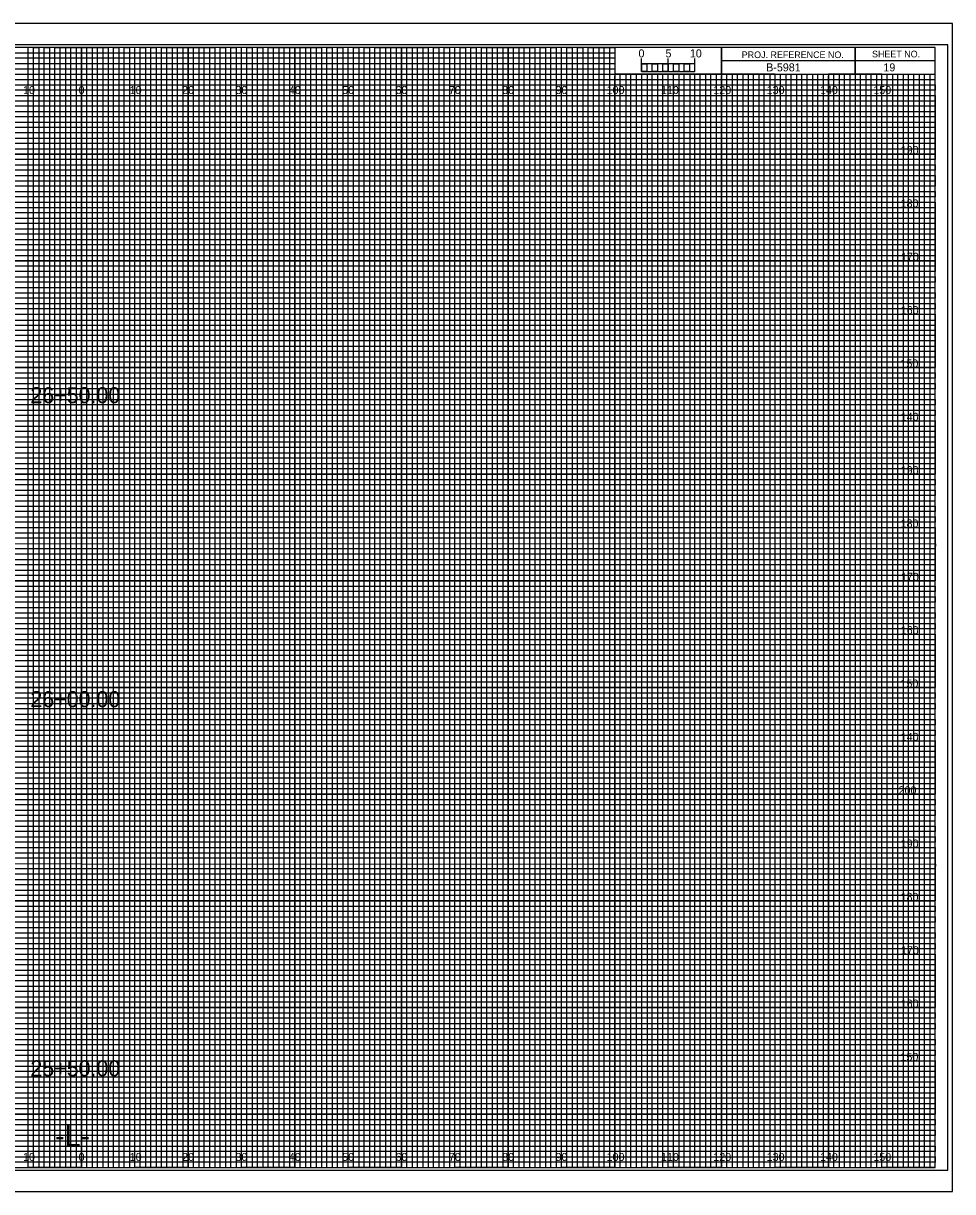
# Model space of a CAD drawing. Extents: x -13 to 323, y -5 to 4174.
# Drawn here: x 149.1 to 323.3, y 2855.5 to 3074.5 of the extents above; entities that cross this region are included whole.
import ezdxf

# ---------------------------------------------------------------- set-up
doc = ezdxf.new("R2010")
doc.units = 0
for name, color, linetype in [('Exist Cross Section Cell', 7, 'Continuous'), ('Exist XS Center Line Elevation Label', 7, 'Continuous'), ('Exist XS Ground Line', 7, 'Continuous'), ('Prop CMT Concrete Structures', 7, 'Continuous'), ('Prop CMT Guardrail Graphics', 7, 'Continuous'), ('Prop CMT Pvmt Course 1', 7, 'Continuous'), ('Prop CMT Pvmt Course 2', 7, 'Continuous'), ('Prop CMT Pvmt Course 3', 7, 'Continuous'), ('Prop CMT Pvmt Surface', 7, 'Continuous'), ('Prop CMT Shld Paved Course 1', 7, 'Continuous'), ('Prop CMT Shld Paved Course 2', 7, 'Continuous'), ('Prop CMT Shld Paved Course 3', 7, 'Continuous'), ('Prop CMT Subgrade Earthwork', 7, 'Continuous'), ('Prop XS Ditch Standard Text', 7, 'Continuous'), ('Prop XS SE Text', 7, 'Continuous'), ('Prop XS Side Slope Text', 7, 'Continuous'), ('Scratch_Level_0', 7, 'Continuous')]:
    doc.layers.add(name, color=color, linetype=linetype)

msp = doc.modelspace()

# ---------------------------------------------------------------- linework, layer by layer
at = {"layer": 'Exist XS Center Line Elevation Label'}
for points in [[(145, 2860), (155, 2860), (155, 3070), (165, 3070), (165, 2860), (175, 2860), (175, 3070), (185, 3070), (185, 2860), (195, 2860), (195, 3070), (205, 3070), (205, 2860), (215, 2860), (215, 3070), (225, 3070), (225, 2860), (235, 2860), (235, 3070), (245, 3070), (245, 2860), (255, 2860), (255, 3070), (259.93, 3070), (260, 3070), (260, 3065), (264.99, 3065), (264.99, 2860), (275, 2860), (275, 3065), (285, 3065), (285, 2860), (295, 2860), (295, 3065), (305, 3065), (305, 2860), (315, 2860), (315, 3065)], [(0, 3065), (275, 3065)], [(0, 3045), (320, 3045), (320, 3055), (0, 3055)], [(0, 3025), (320, 3025), (320, 3035), (0, 3035)], [(0, 3005), (320, 3005), (320, 3015), (0, 3015)], [(0, 2985), (320, 2985), (320, 2995), (0, 2995)], [(0, 2965), (320, 2965), (320, 2975), (0, 2975)], [(0, 2945), (320, 2945), (320, 2955), (0, 2955)], [(0, 2925), (320, 2925), (320, 2935), (0, 2935)], [(0, 2905), (320, 2905), (320, 2915), (0, 2915)], [(0, 2885), (320, 2885), (320, 2895), (0, 2895)], [(0, 2865), (320, 2865), (320, 2875), (0, 2875)]]:
    msp.add_lwpolyline(points, dxfattribs=at)
at = {"layer": 'Exist XS Ground Line'}
for p, q in [((150, 3070), (140, 3070)), ((150, 2860), (150, 3070)), ((170, 3070), (160, 3070)), ((160, 3070), (160, 2860)), ((170, 2860), (170, 3070)), ((190, 3070), (180, 3070)), ((180, 3070), (180, 2860)), ((190, 2860), (190, 3070)), ((210, 3070), (200, 3070)), ((200, 3070), (200, 2860)), ((210, 2860), (210, 3070)), ((230, 3070), (220, 3070)), ((220, 3070), (220, 2860)), ((230, 2860), (230, 3070)), ((250, 3070), (240, 3070)), ((240, 3070), (240, 2860)), ((250, 2860), (250, 3070)), ((260, 3070), (260, 2860)), ((270, 2860), (270, 3065)), ((290, 3065), (280, 3065)), ((280, 3065), (280, 2860)), ((290, 2860), (290, 3065)), ((310, 3065), (300, 3065)), ((300, 3065), (300, 2860)), ((310, 2860), (310, 3065)), ((160, 2860), (150, 2860)), ((180, 2860), (170, 2860)), ((200, 2860), (190, 2860)), ((220, 2860), (210, 2860)), ((240, 2860), (230, 2860)), ((260, 2860), (250, 2860)), ((280, 2860), (270, 2860)), ((300, 2860), (290, 2860)), ((320, 2860), (310, 2860)), ((320, 2860), (320, 2860))]:
    msp.add_line(p, q, dxfattribs=at)
for points in [[(0, 3060), (320, 3060), (320, 3050), (0, 3050)], [(0, 3040), (320, 3040), (320, 3030), (0, 3030)], [(0, 3020), (320, 3020), (320, 3010), (0, 3010)], [(0, 3000), (320, 3000), (320, 2990), (0, 2990)], [(0, 2980), (320, 2980), (320, 2970), (0, 2970)], [(0, 2960), (320, 2960), (320, 2950), (0, 2950)], [(0, 2940), (320, 2940), (320, 2930), (0, 2930)], [(0, 2920), (320, 2920), (320, 2910), (0, 2910)], [(0, 2900), (320, 2900), (320, 2890), (0, 2890)], [(0, 2880), (320, 2880), (320, 2870), (0, 2870)]]:
    msp.add_lwpolyline(points, dxfattribs=at)
at = {"layer": 'Prop CMT Pvmt Course 1'}
for p, q in [((323.3, 3074.5), (-13.4, 3074.5)), ((-13.4, 2855.5), (323.3, 2855.5))]:
    msp.add_line(p, q, dxfattribs=at)
at = {"layer": 'Prop CMT Pvmt Course 2'}
msp.add_lwpolyline([(-13.4, 2855.5), (323.3, 2855.5), (323.3, 3074.5), (-13.4, 3074.5)], close=True, dxfattribs=at)
at = {"layer": 'Prop CMT Pvmt Course 3'}
msp.add_lwpolyline([(-10.8, 2859.5), (322.4, 2859.5), (322.4, 3070.5), (-10.8, 3070.5)], close=True, dxfattribs=at)
at = {"layer": 'Prop CMT Shld Paved Course 1'}
for p, q in [((305, 3070), (305, 3065)), ((305, 3065), (305, 3070)), ((280, 3067.5), (280, 3065)), ((320, 3067.49), (280, 3067.49)), ((280, 3065), (320, 3065))]:
    msp.add_line(p, q, dxfattribs=at)
for points in [[(320, 3070), (0, 3070), (0, 2860), (320, 2860)], [(280, 3070), (260, 3070), (260, 3065.03), (280, 3065.03)], [(320, 3070), (280, 3070), (280, 3065), (320, 3065)]]:
    msp.add_lwpolyline(points, close=True, dxfattribs=at)
at = {"layer": 'Prop CMT Shld Paved Course 2'}
for p, q in [((267, 3065), (266.01, 3065)), ((266.01, 3065), (266.01, 2860)), ((267, 2860), (267, 3065)), ((269, 3065), (268, 3065)), ((268, 3065), (268, 2860)), ((269, 2860), (269, 3065)), ((266.01, 2860), (265, 2860)), ((268, 2860), (267, 2860))]:
    msp.add_line(p, q, dxfattribs=at)
for points in [[(150, 2860), (151, 2860), (151, 3070), (152, 3070), (152, 2860)], [(152, 2860), (153, 2860), (153, 3070), (154, 3070), (154, 2860)], [(155, 2860), (156, 2860), (156, 3070), (157, 3070), (157, 2860)], [(157, 2860), (158, 2860), (158, 3070), (159, 3070), (159, 2860)], [(160, 2860), (161, 2860), (161, 3070), (162, 3070), (162, 2860)], [(162, 2860), (163, 2860), (163, 3070), (164, 3070), (164, 2860)], [(165, 2860), (166, 2860), (166, 3070), (167, 3070), (167, 2860)], [(167, 2860), (168, 2860), (168, 3070), (169, 3070), (169, 2860)], [(170, 2860), (171, 2860), (171, 3070), (172, 3070), (172, 2860)], [(172, 2860), (173, 2860), (173, 3070), (174, 3070), (174, 2860)], [(175, 2860), (176, 2860), (176, 3070), (177, 3070), (177, 2860)], [(177, 2860), (178, 2860), (178, 3070), (179, 3070), (179, 2860)], [(180, 2860), (181, 2860), (181, 3070), (182, 3070), (182, 2860)], [(182, 2860), (183, 2860), (183, 3070), (184, 3070), (184, 2860)], [(185, 2860), (186, 2860), (186, 3070), (187, 3070), (187, 2860)], [(187, 2860), (188, 2860), (188, 3070), (189, 3070), (189, 2860)], [(190, 2860), (191, 2860), (191, 3070), (192, 3070), (192, 2860)], [(192, 2860), (193, 2860), (193, 3070), (194, 3070), (194, 2860)], [(195, 2860), (196, 2860), (196, 3070), (197, 3070), (197, 2860)], [(197, 2860), (198, 2860), (198, 3070), (199, 3070), (199, 2860)], [(200, 2860), (201, 2860), (201, 3070), (202, 3070), (202, 2860)], [(202, 2860), (203, 2860), (203, 3070), (204, 3070), (204, 2860)], [(205, 2860), (206, 2860), (206, 3070), (207, 3070), (207, 2860)], [(207, 2860), (208, 2860), (208, 3070), (209, 3070), (209, 2860)], [(210, 2860), (211, 2860), (211, 3070), (212, 3070), (212, 2860)], [(212, 2860), (213, 2860), (213, 3070), (214, 3070), (214, 2860)], [(215, 2860), (216, 2860), (216, 3070), (217, 3070), (217, 2860)], [(217, 2860), (218, 2860), (218, 3070), (219, 3070), (219, 2860)], [(220, 2860), (221, 2860), (221, 3070), (222, 3070), (222, 2860)], [(222, 2860), (223, 2860), (223, 3070), (224, 3070), (224, 2860)], [(225, 2860), (226, 2860), (226, 3070), (227, 3070), (227, 2860)], [(227, 2860), (228, 2860), (228, 3070), (229, 3070), (229, 2860)], [(230, 2860), (231, 2860), (231, 3070), (232, 3070), (232, 2860)], [(232, 2860), (233, 2860), (233, 3070), (234, 3070), (234, 2860)], [(235, 2860), (236, 2860), (236, 3070), (237, 3070), (237, 2860)], [(237, 2860), (238, 2860), (238, 3070), (239, 3070), (239, 2860)], [(240, 2860), (241, 2860), (241, 3070), (242, 3070), (242, 2860)], [(242, 2860), (243, 2860), (243, 3070), (244, 3070), (244, 2860)], [(245, 2860), (246, 2860), (246, 3070), (247, 3070), (247, 2860)], [(247, 2860), (248, 2860), (248, 3070), (249, 3070), (249, 2860)], [(250, 2860), (251, 2860), (251, 3070), (252, 3070), (252, 2860)], [(252, 2860), (253, 2860), (253, 3070), (254, 3070), (254, 2860)], [(255, 2860), (256, 2860), (256, 3070), (257, 3070), (257, 2860)], [(257, 2860), (258, 2860), (258, 3070), (259, 3070), (259, 2860)], [(260, 2860), (261, 2860), (261, 3065), (262.02, 3065), (262.02, 2860)], [(262, 2860), (263, 2860), (263, 3065), (263.99, 3065), (263.99, 2860)], [(270, 2860), (270.98, 2860), (270.98, 3065), (272, 3065), (272, 2860)], [(272, 2860), (273, 2860), (273, 3065), (274.05, 3065), (274.05, 2860)], [(275, 2860), (276, 2860), (276, 3065), (277, 3065), (277, 2860)], [(277, 2860), (278, 2860), (278, 3065), (279, 3065), (279, 2860)], [(280, 2860), (281, 2860), (281, 3065), (282, 3065), (282, 2860)], [(282, 2860), (283, 2860), (283, 3065), (284, 3065), (284, 2860)], [(285, 2860), (286, 2860), (286, 3065), (287, 3065), (287, 2860)], [(287, 2860), (288, 2860), (288, 3065), (289, 3065), (289, 2860)], [(290, 2860), (291, 2860), (291, 3065), (292, 3065), (292, 2860)], [(292, 2860), (293, 2860), (293, 3065), (294, 3065), (294, 2860)], [(295, 2860), (296, 2860), (296, 3065), (297, 3065), (297, 2860)], [(297, 2860), (298, 2860), (298, 3065), (299, 3065), (299, 2860)], [(300, 2860), (301, 2860), (301, 3065), (302, 3065), (302, 2860)], [(302, 2860), (303, 2860), (303, 3065), (304, 3065), (304, 2860)], [(305, 2860), (306, 2860), (306, 3065), (307, 3065), (307, 2860)], [(307, 2860), (308, 2860), (308, 3065), (309, 3065), (309, 2860)], [(310, 2860), (311, 2860), (311, 3065), (312, 3065), (312, 2860)], [(312, 2860), (313, 2860), (313, 3065), (314, 3065), (314, 2860)], [(315, 2860), (316, 2860), (316, 3065), (317, 3065), (317, 2860)], [(317, 2860), (318, 2860), (318, 3065), (319, 3065), (319, 2860)]]:
    msp.add_lwpolyline(points, dxfattribs=at)
at = {"layer": 'Prop CMT Shld Paved Course 3'}
for p, q in [((265, 3065.49), (265, 3067.9)), ((265, 3066.9), (265, 3067.9)), ((270, 3065.49), (270, 3067.9)), ((275, 3065.49), (275, 3067.9)), ((275, 3066.9), (275, 3067.9))]:
    msp.add_line(p, q, dxfattribs=at)
for points in [[(275, 3066.9), (265, 3066.9), (265, 3065.49), (275, 3065.49)], [(265, 3066.9), (266, 3066.9), (266, 3065.49), (265, 3065.49)], [(267, 3066.9), (268, 3066.9), (268, 3065.49), (267, 3065.49)], [(269, 3066.9), (270, 3066.9), (270, 3065.49), (269, 3065.49)], [(271, 3066.9), (272, 3066.9), (272, 3065.49), (271, 3065.49)], [(273, 3066.9), (274, 3066.9), (274, 3065.49), (273, 3065.49)]]:
    msp.add_lwpolyline(points, close=True, dxfattribs=at)
at = {"layer": 'Prop CMT Subgrade Earthwork'}
for p, q in [((150, 2860), (150, 3070)), ((160, 2860), (160, 3070)), ((170, 2860), (170, 3070)), ((180, 2860), (180, 3070)), ((190, 2860), (190, 3070)), ((200, 2860), (200, 3070)), ((210, 2860), (210, 3070)), ((220, 2860), (220, 3070)), ((230, 2860), (230, 3070)), ((240, 2860), (240, 3070)), ((250, 2860), (250, 3070)), ((260, 2860), (260, 3064.69)), ((270, 2860), (270, 3064.69)), ((280, 2860), (280, 3064.69)), ((290, 2860), (290, 3064.69)), ((300, 2860), (300, 3064.69)), ((310, 2860), (310, 3064.69)), ((0, 3060), (320, 3060)), ((0, 3050), (320, 3050)), ((0, 3040), (320, 3040)), ((0, 3030), (320, 3030)), ((0, 3020), (320, 3020)), ((0, 3010), (320, 3010)), ((0, 3000), (320, 3000)), ((0, 2990), (320, 2990)), ((0, 2980), (320, 2980)), ((0, 2970), (320, 2970)), ((0, 2960), (320, 2960)), ((0, 2950), (320, 2950)), ((0, 2940), (320, 2940)), ((0, 2930), (320, 2930)), ((0, 2920), (320, 2920)), ((0, 2910), (320, 2910)), ((0, 2900), (320, 2900)), ((0, 2890), (320, 2890)), ((0, 2880), (320, 2880)), ((0, 2870), (320, 2870))]:
    msp.add_line(p, q, dxfattribs=at)
at = {"layer": 'Scratch_Level_0'}
for p, q in [((0, 3069), (260, 3069)), ((260, 3069), (260, 3067.98)), ((260, 3067.98), (0, 3067.98)), ((0, 3067), (260, 3067)), ((260, 3067), (260, 3065.89)), ((260, 3065.89), (0, 3065.89)), ((0, 3064), (320, 3064))]:
    msp.add_line(p, q, dxfattribs=at)
for points in [[(0, 3063), (270, 3063), (320, 3063), (320, 3062), (0, 3062)], [(0, 3061), (320, 3061), (320, 3059), (0, 3059)], [(0, 3058), (320, 3058), (320, 3057), (0, 3056.98)], [(0, 3056), (320, 3056), (320, 3054), (0, 3054)], [(0, 3053), (320, 3053), (320, 3052), (0, 3052)], [(0, 3051), (320, 3051), (320, 3049), (0, 3049)], [(0, 3048), (320, 3048), (320, 3047), (0, 3047)], [(0, 3046), (320, 3046), (320, 3044), (0, 3044)], [(0, 3043), (320, 3043), (320, 3042), (0, 3042)], [(0, 3041), (320, 3041), (320, 3039), (0, 3039)], [(0, 3038), (320, 3038), (320, 3037), (0, 3037)], [(0, 3036), (320, 3036), (320, 3033.95), (320, 3033), (320, 3032), (0, 3032)], [(0, 3034), (320, 3034), (320, 3033), (0, 3033)], [(0, 3031), (320, 3031), (320, 3029), (0, 3029.03)], [(0, 3029.03), (320, 3029), (320, 3028), (0, 3028)], [(0, 3027), (320, 3027), (320, 3026), (0, 3026)], [(0, 3024), (320, 3024), (320, 3023), (0, 3023)], [(0, 3022), (320, 3022), (320, 3021), (0, 3021)], [(-0.07, 3018.89), (320, 3018.89), (320, 3017.88), (-0.07, 3017.88)], [(0, 3017), (320, 3017), (320, 3016), (0, 3016)], [(0, 3014), (320, 3014), (320, 3013), (0, 3013)], [(0, 3012), (320, 3012), (320, 3011), (0, 3011)], [(0, 3009), (320, 3009), (320, 3008), (0, 3008)], [(0, 3007), (320, 3007), (320, 3006), (0, 3006)], [(0, 3004), (320, 3004), (320, 3003), (0, 3003)], [(0, 3002), (320, 3002), (320, 3001), (0, 3001)], [(0, 2999), (320, 2999), (319.99, 2997.98), (0, 2998)], [(0, 2997), (320, 2997), (320, 2996), (0, 2996)], [(0, 2994), (320, 2994), (320, 2993), (0, 2993)], [(0, 2992), (320, 2992), (320, 2991), (0, 2991)], [(0, 2989), (320, 2989), (320, 2988), (0, 2988)], [(0, 2987), (320, 2987), (320, 2986), (0, 2986)], [(0, 2984), (320, 2984), (320, 2983), (0, 2983)], [(0, 2982), (320, 2982), (320, 2981), (0, 2981)], [(0, 2979), (320, 2979), (320, 2978), (0, 2978)], [(0, 2976.99), (320.07, 2976.91), (320, 2976), (0, 2976)], [(0, 2974), (320, 2974), (320, 2973), (0, 2973)], [(0, 2972), (320, 2972), (320, 2971), (0, 2971)], [(0, 2969), (320, 2969), (320, 2968), (0, 2968)], [(0, 2967), (320, 2967), (320, 2966), (0, 2966)], [(0, 2964), (320, 2964), (320, 2963), (0, 2963)], [(0, 2962), (320, 2962), (320, 2961), (0, 2961)], [(0, 2959), (320, 2959), (320, 2958), (0, 2958)], [(0, 2957), (320, 2957), (320, 2956), (0, 2956)], [(0, 2954), (320, 2954), (320, 2953), (0, 2953)], [(0, 2952), (320, 2952), (320, 2951), (0, 2951)], [(0, 2949), (320, 2949), (320, 2948), (0, 2948)], [(0, 2947), (320, 2947), (320, 2946), (0, 2946)], [(0, 2944), (320, 2944), (320, 2943), (0, 2943)], [(0, 2942), (320, 2942), (320, 2941), (0, 2941)], [(0, 2939), (320, 2939), (319.99, 2937.98), (0, 2938)], [(0, 2937), (320, 2937), (320, 2936), (0, 2936)], [(0, 2934), (320, 2934), (320, 2933), (0, 2933)], [(0, 2932), (320, 2932), (320, 2931), (0, 2931)], [(0, 2929), (320, 2929), (320, 2928), (0, 2928)], [(0, 2927), (320, 2927), (320, 2926), (0, 2926)], [(0, 2924), (320, 2924), (320, 2923), (0, 2923)], [(0, 2922), (320, 2922), (320, 2921), (0, 2921)], [(0, 2919), (320, 2919), (320, 2918), (0, 2918)], [(0, 2916.99), (320.07, 2916.91), (320, 2916), (0, 2916)], [(0, 2914), (320, 2914), (320, 2913), (0, 2913)], [(0, 2912), (320, 2912), (320, 2911), (0, 2911)], [(0, 2909), (320, 2909), (320, 2908), (0, 2908)], [(0, 2907), (320, 2907), (320, 2906), (0, 2906)], [(0, 2904), (320, 2904), (320, 2903), (0, 2903)], [(0, 2902), (320, 2902), (320, 2901), (0, 2901)], [(0, 2899), (320, 2899), (320, 2898), (0, 2898)], [(0, 2897), (320, 2897), (320, 2896), (0, 2896)], [(0, 2894), (320, 2894), (320, 2893), (0, 2893)], [(0, 2892), (320, 2892), (320, 2891), (0, 2891)], [(0, 2889), (320, 2889), (320, 2888), (0, 2888)], [(0, 2887), (320, 2887), (320, 2886), (0, 2886)], [(0, 2884), (320, 2884), (320, 2883), (0, 2883)], [(0, 2882), (320, 2882), (320, 2881), (0, 2881)], [(0, 2879), (320, 2879), (320, 2878), (0, 2878)], [(0, 2877), (320, 2877), (320, 2876), (0, 2876)], [(0, 2874), (320, 2874), (320, 2873), (0, 2873)], [(0, 2872), (320, 2872), (320, 2871), (0, 2871)], [(0, 2869), (320, 2869), (320, 2868), (0, 2868)], [(0, 2867), (320, 2867), (320, 2866), (0, 2866)], [(0, 2864), (320, 2864), (320, 2863), (0, 2863)], [(0, 2862), (320, 2862), (320, 2861), (0, 2861)]]:
    msp.add_lwpolyline(points, dxfattribs=at)

# ---------------------------------------------------------------- texts
at = {"layer": 'Exist Cross Section Cell'}
for s, p in [('10', (149.04, 3061.25)), ('0', (159.45, 3061.25)), ('0', (159.45, 3061.25)), ('10', (169.04, 3061.25)), ('20', (178.86, 3061.25)), ('30', (188.86, 3061.25)), ('40', (198.86, 3061.25)), ('50', (208.86, 3061.25)), ('60', (218.86, 3061.25)), ('70', (228.86, 3061.25)), ('80', (238.86, 3061.25)), ('90', (248.86, 3061.25)), ('100', (258.44, 3061.25)), ('110', (268.62, 3061.25)), ('120', (278.44, 3061.25)), ('130', (288.44, 3061.25)), ('140', (298.44, 3061.25)), ('150', (308.44, 3061.25)), ('10', (149.04, 2861.25)), ('0', (159.45, 2861.25)), ('0', (159.45, 2861.25)), ('10', (169.04, 2861.25)), ('20', (178.86, 2861.25)), ('30', (188.86, 2861.25)), ('40', (198.86, 2861.25)), ('50', (208.86, 2861.25)), ('60', (218.86, 2861.25)), ('70', (228.86, 2861.25)), ('80', (238.86, 2861.25)), ('90', (248.86, 2861.25)), ('100', (258.44, 2861.25)), ('110', (268.62, 2861.25)), ('120', (278.44, 2861.25)), ('130', (288.44, 2861.25)), ('140', (298.44, 2861.25)), ('150', (308.44, 2861.25))]:
    msp.add_text(s, height=1.5, dxfattribs=at).set_placement(p)
at = {"layer": 'Prop CMT Concrete Structures'}
for s, p in [('26+50.00', (150.41, 3003.3)), ('26+00.00', (150.41, 2946.32)), ('25+50.00', (150.41, 2877.12))]:
    msp.add_text(s, height=3, dxfattribs=at).set_placement(p)
at = {"layer": 'Prop CMT Guardrail Graphics'}
for s, p in [('190', (313.57, 3050)), ('180', (313.55, 3040)), ('170', (313.61, 3030)), ('160', (313.57, 3020)), ('150', (313.52, 3010)), ('140', (313.57, 3000)), ('190', (313.57, 2990)), ('180', (313.55, 2980)), ('170', (313.61, 2970)), ('160', (313.57, 2960)), ('150', (313.52, 2950)), ('140', (313.57, 2940)), ('200', (313.17, 2930)), ('190', (313.57, 2920)), ('180', (313.55, 2910)), ('170', (313.61, 2900)), ('160', (313.57, 2890)), ('150', (313.52, 2880))]:
    msp.add_text(s, height=1.5, dxfattribs=at).set_placement(p)
at = {"layer": 'Prop CMT Pvmt Surface'}
for s, p in [('5', (269.47, 3068.12)), ('10', (274.04, 3068.12))]:
    msp.add_text(s, height=1.5, dxfattribs=at).set_placement(p)
at = {"layer": 'Prop CMT Shld Paved Course 1'}
for s, p in [('PROJ. REFERENCE NO.', (283.77, 3067.99)), ('SHEET NO.', (308.19, 3068.12))]:
    msp.add_text(s, height=1.25, dxfattribs=at).set_placement(p)
at = {"layer": 'Prop CMT Shld Paved Course 3'}
msp.add_text('0', height=1.5, dxfattribs=at).set_placement((264.41, 3068.12))
at = {"layer": 'Prop XS Ditch Standard Text'}
msp.add_text('-L-', height=4, dxfattribs=at).set_placement((155.06, 2864))
at = {"layer": 'Prop XS SE Text'}
msp.add_text(' B-5981', height=1.5, dxfattribs=at).set_placement((287.79, 3065.5))
at = {"layer": 'Prop XS Side Slope Text'}
msp.add_text('19', height=1.5, dxfattribs=at).set_placement((310.32, 3065.5))

doc.saveas('drawing.dxf')
